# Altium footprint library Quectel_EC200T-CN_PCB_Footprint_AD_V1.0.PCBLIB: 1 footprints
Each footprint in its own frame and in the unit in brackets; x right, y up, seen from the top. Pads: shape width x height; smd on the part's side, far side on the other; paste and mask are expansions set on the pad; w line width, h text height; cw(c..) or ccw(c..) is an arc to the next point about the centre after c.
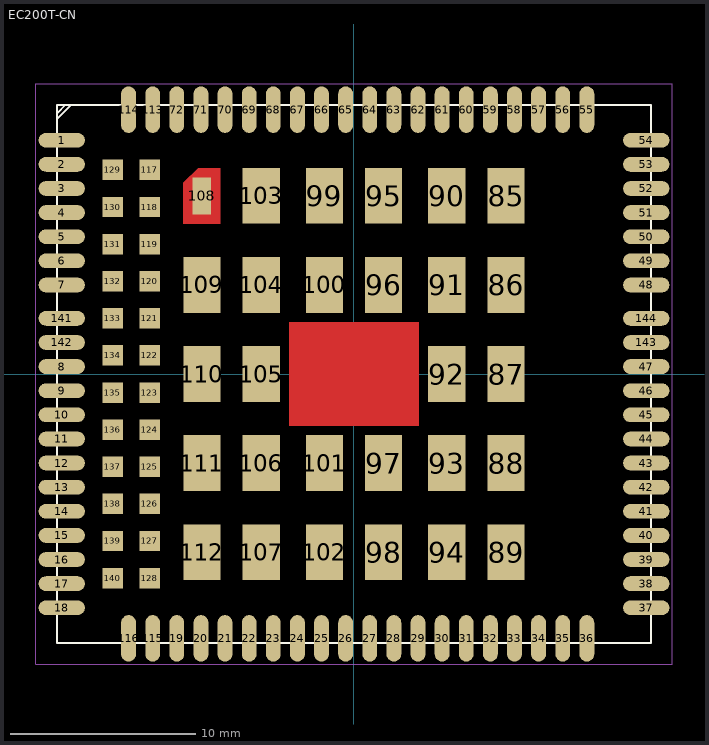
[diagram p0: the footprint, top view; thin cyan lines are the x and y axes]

## EC200T-CN [mm]
height 2.6
pads (132):
  oval 2.5x0.8 smd mask+0.05: 1(-15.75,12.6) 2(-15.75,11.3) 3(-15.75,10) 4(-15.75,8.7) 5(-15.75,7.4) 6(-15.75,6.1) 7(-15.75,4.8) 8(-15.75,0.4) 9(-15.75,-0.9) 10(-15.75,-2.2) 11(-15.75,-3.5) 12(-15.75,-4.8) 13(-15.75,-6.1) 14(-15.75,-7.4) 15(-15.75,-8.7) 16(-15.75,-10) 17(-15.75,-11.3) 18(-15.75,-12.6) 37(15.75,-12.6) 38(15.75,-11.3) 39(15.75,-10) 40(15.75,-8.7) 41(15.75,-7.4) 42(15.75,-6.1) 43(15.75,-4.8) 44(15.75,-3.5) 45(15.75,-2.2) 46(15.75,-0.9) 47(15.75,0.4) 48(15.75,4.8) 49(15.75,6.1) 50(15.75,7.4) 51(15.75,8.7) 52(15.75,10) 53(15.75,11.3) 54(15.75,12.6) 141(-15.75,3) 142(-15.75,1.7) 143(15.75,1.7) 144(15.75,3)
  oval 0.8x2.5 smd mask+0.05: 19(-9.55,-14.25) 20(-8.25,-14.25) 21(-6.95,-14.25) 22(-5.65,-14.25) 23(-4.35,-14.25) 24(-3.05,-14.25) 25(-1.75,-14.25) 26(-0.45,-14.25) 27(0.85,-14.25) 28(2.15,-14.25) 29(3.45,-14.25) 30(4.75,-14.25) 31(6.05,-14.25) 32(7.35,-14.25) 33(8.65,-14.25) 34(9.95,-14.25) 35(11.25,-14.25) 36(12.55,-14.25) 55(12.55,14.25) 56(11.25,14.25) 57(9.95,14.25) 58(8.65,14.25) 59(7.35,14.25) 60(6.05,14.25) 61(4.75,14.25) 62(3.45,14.25) 63(2.15,14.25) 64(0.85,14.25) 65(-0.45,14.25) 66(-1.75,14.25) 67(-3.05,14.25) 68(-4.35,14.25) 69(-5.65,14.25) 70(-6.95,14.25) 71(-8.25,14.25) 72(-9.55,14.25) 113(-10.85,14.25) 114(-12.15,14.25) 115(-10.85,-14.25) 116(-12.15,-14.25)
  rect 2x3 smd mask+0.05: 85(8.2,9.6) 86(8.2,4.8) 87(8.2,0) 88(8.2,-4.8) 89(8.2,-9.6) 90(5,9.6) 91(5,4.8) 92(5,0) 93(5,-4.8) 94(5,-9.6) 95(1.6,9.6) 96(1.6,4.8) 97(1.6,-4.8) 98(1.6,-9.6) 99(-1.6,9.6) 100(-1.6,4.8) 101(-1.6,-4.8) 102(-1.6,-9.6) 103(-5,9.6) 104(-5,4.8) 105(-5,0) 106(-5,-4.8) 107(-5,-9.6) 109(-8.2,4.8) 110(-8.2,0) 111(-8.2,-4.8) 112(-8.2,-9.6)
  rect 1x2 smd mask+0.05: 108(-8.2,9.6)
  rect 1.1x1.1 smd mask+0.05: 117(-11,11) 118(-11,9) 119(-11,7) 120(-11,5) 121(-11,3) 122(-11,1) 123(-11,-1) 124(-11,-3) 125(-11,-5) 126(-11,-7) 127(-11,-9) 128(-11,-11) 129(-13,11) 130(-13,9) 131(-13,7) 132(-13,5) 133(-13,3) 134(-13,1) 135(-13,-1) 136(-13,-3) 137(-13,-5) 138(-13,-7) 139(-13,-9) 140(-13,-11)
Top Layer:
  pour cut-out: 3.5,2.8 -3.5,2.8 -3.5,-2.8 3.5,-2.8
  region: -9.2,10.3 -8.4,11.1 -7.2,11.1 -7.2,8.1 -9.2,8.1
Top Overlay:
  lines w0.102: -16,13.75 -15.25,14.5 ; -16,14.5 -16,14.05 -15.55,14.5 -16,14.5 ; -16,14.5 -16,-14.5 16,-14.5 16,14.5 -16,14.5
Top Paste:
  region: -9.2,10.3 -8.4,11.1 -7.2,11.1 -7.2,8.1 -9.2,8.1
Top Solder:
  region: -9.25,8.05 -7.15,8.05 -7.15,11.15 -8.45,11.15 -9.25,10.35
Mechanical 1:
  lines w0.01: -17.15,-15.65 -17.15,15.65 17.15,15.65 17.15,-15.65 -17.15,-15.65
